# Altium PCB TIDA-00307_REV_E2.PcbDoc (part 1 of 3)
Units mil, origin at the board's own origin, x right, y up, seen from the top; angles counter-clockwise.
Board outline 2360 x 3725 mil, 4 copper layers (Top Layer, L2_GND-PLANE, L3_PWR-PLANE, Bottom Layer), stack 90 mil thick; 312 components, 149 nets, 674 pads, 257 vias.
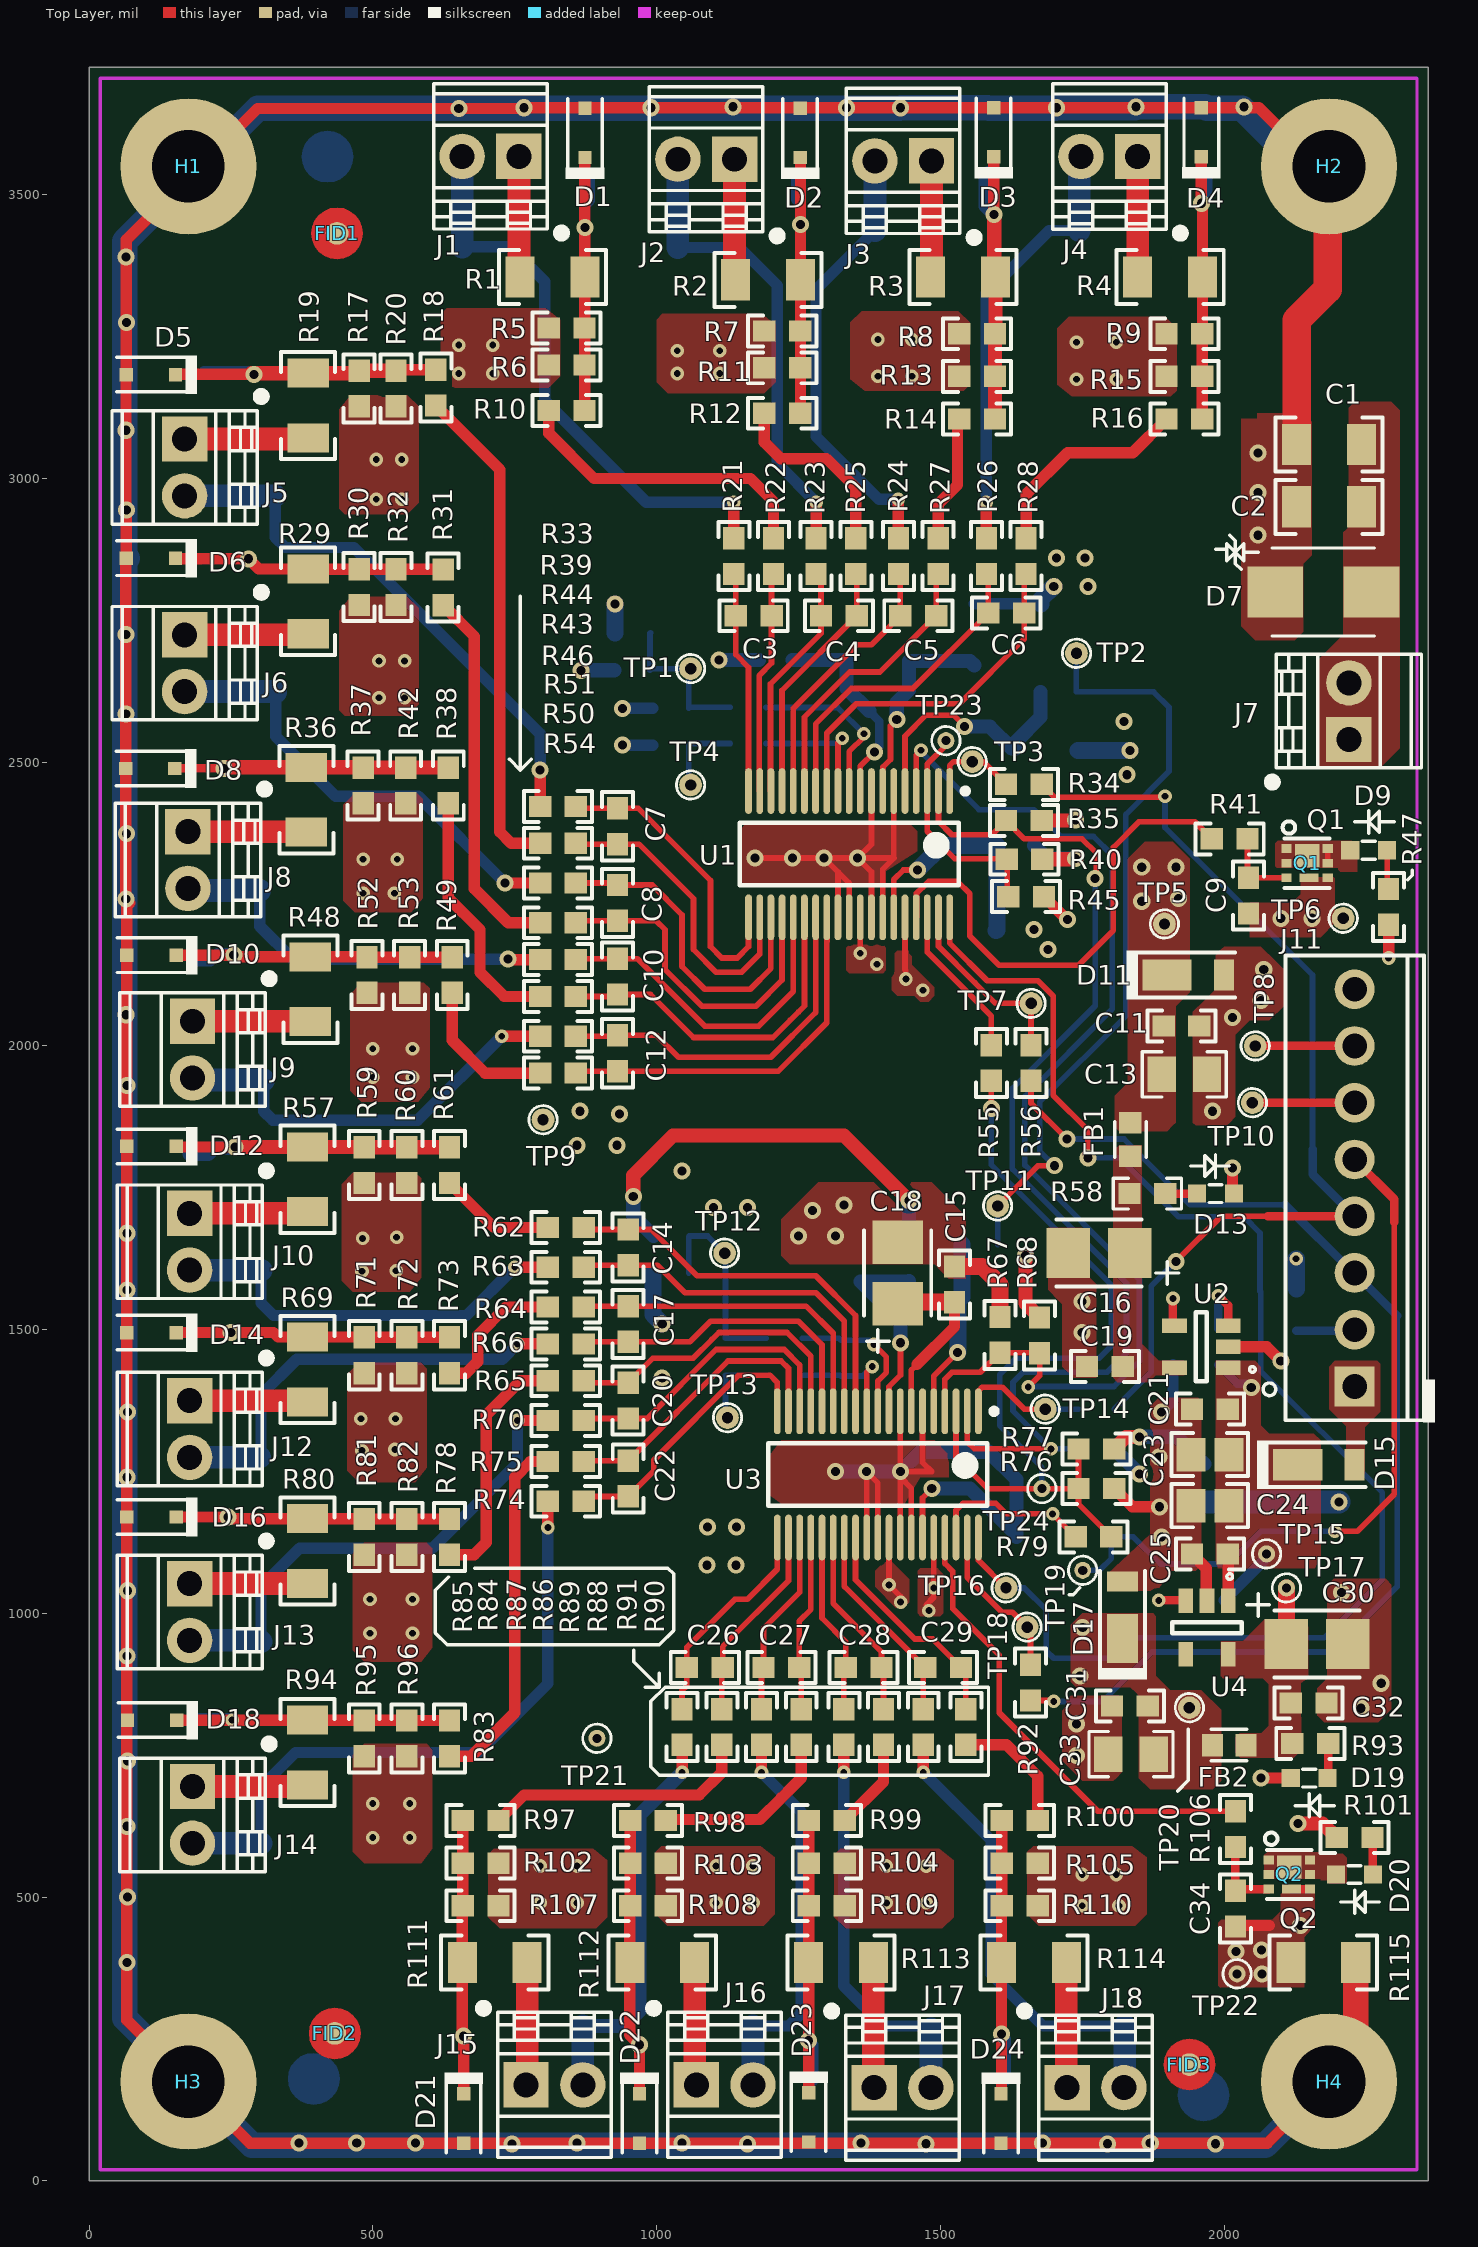
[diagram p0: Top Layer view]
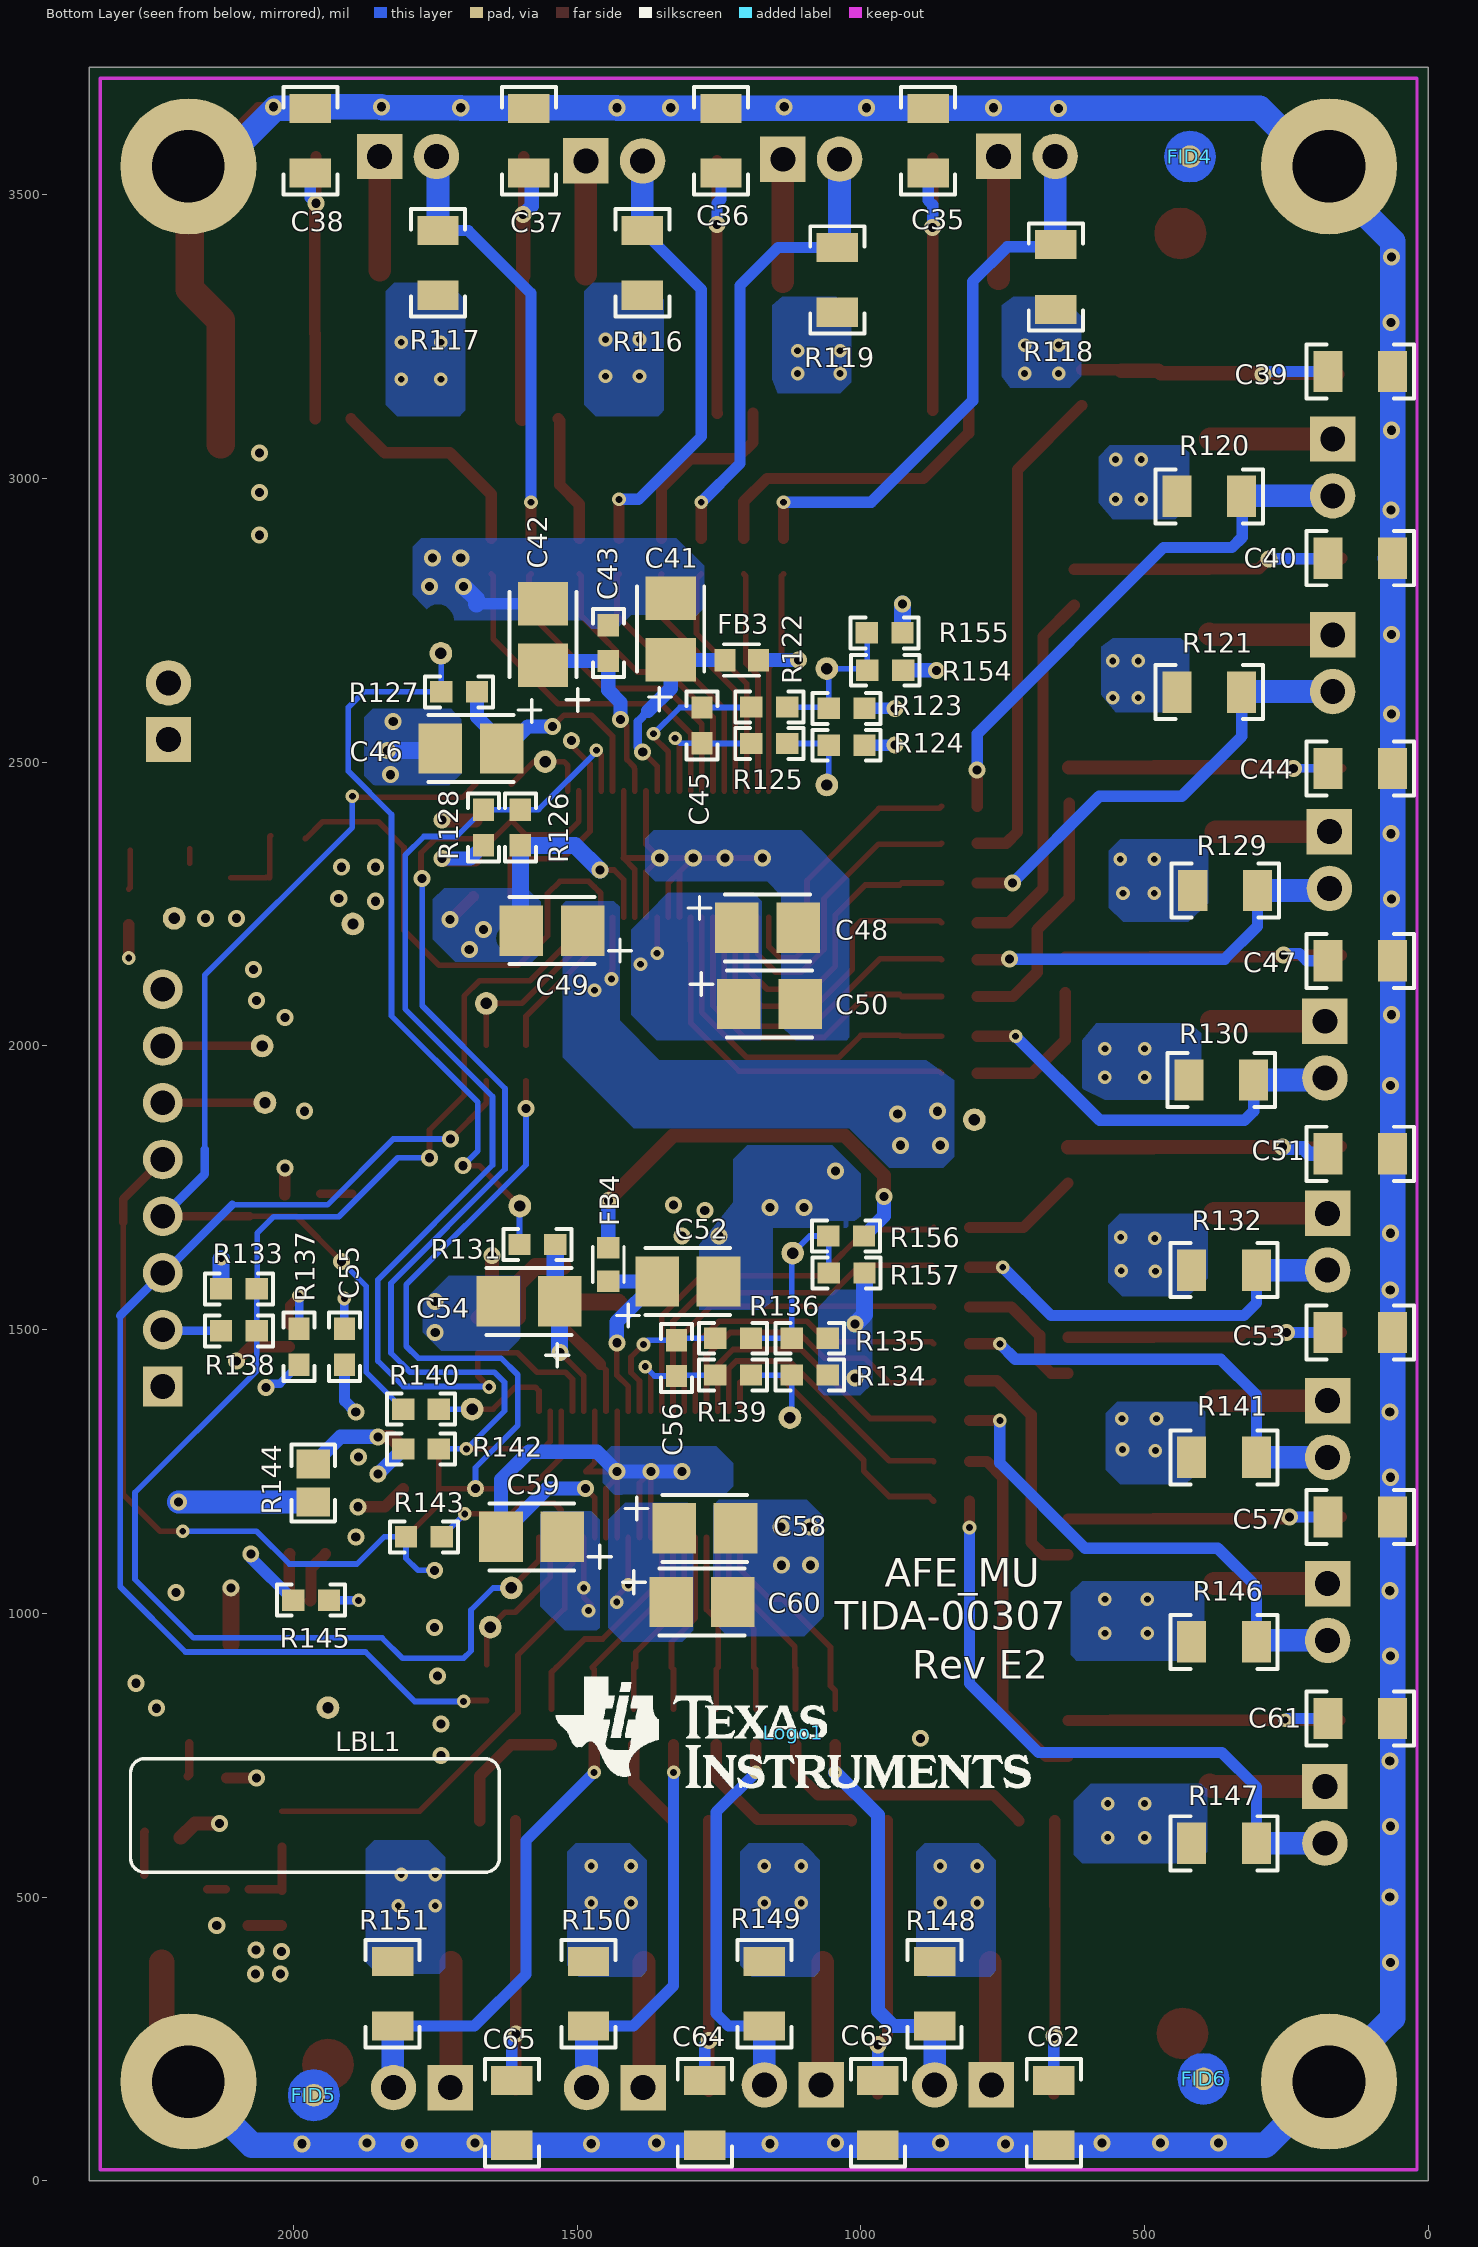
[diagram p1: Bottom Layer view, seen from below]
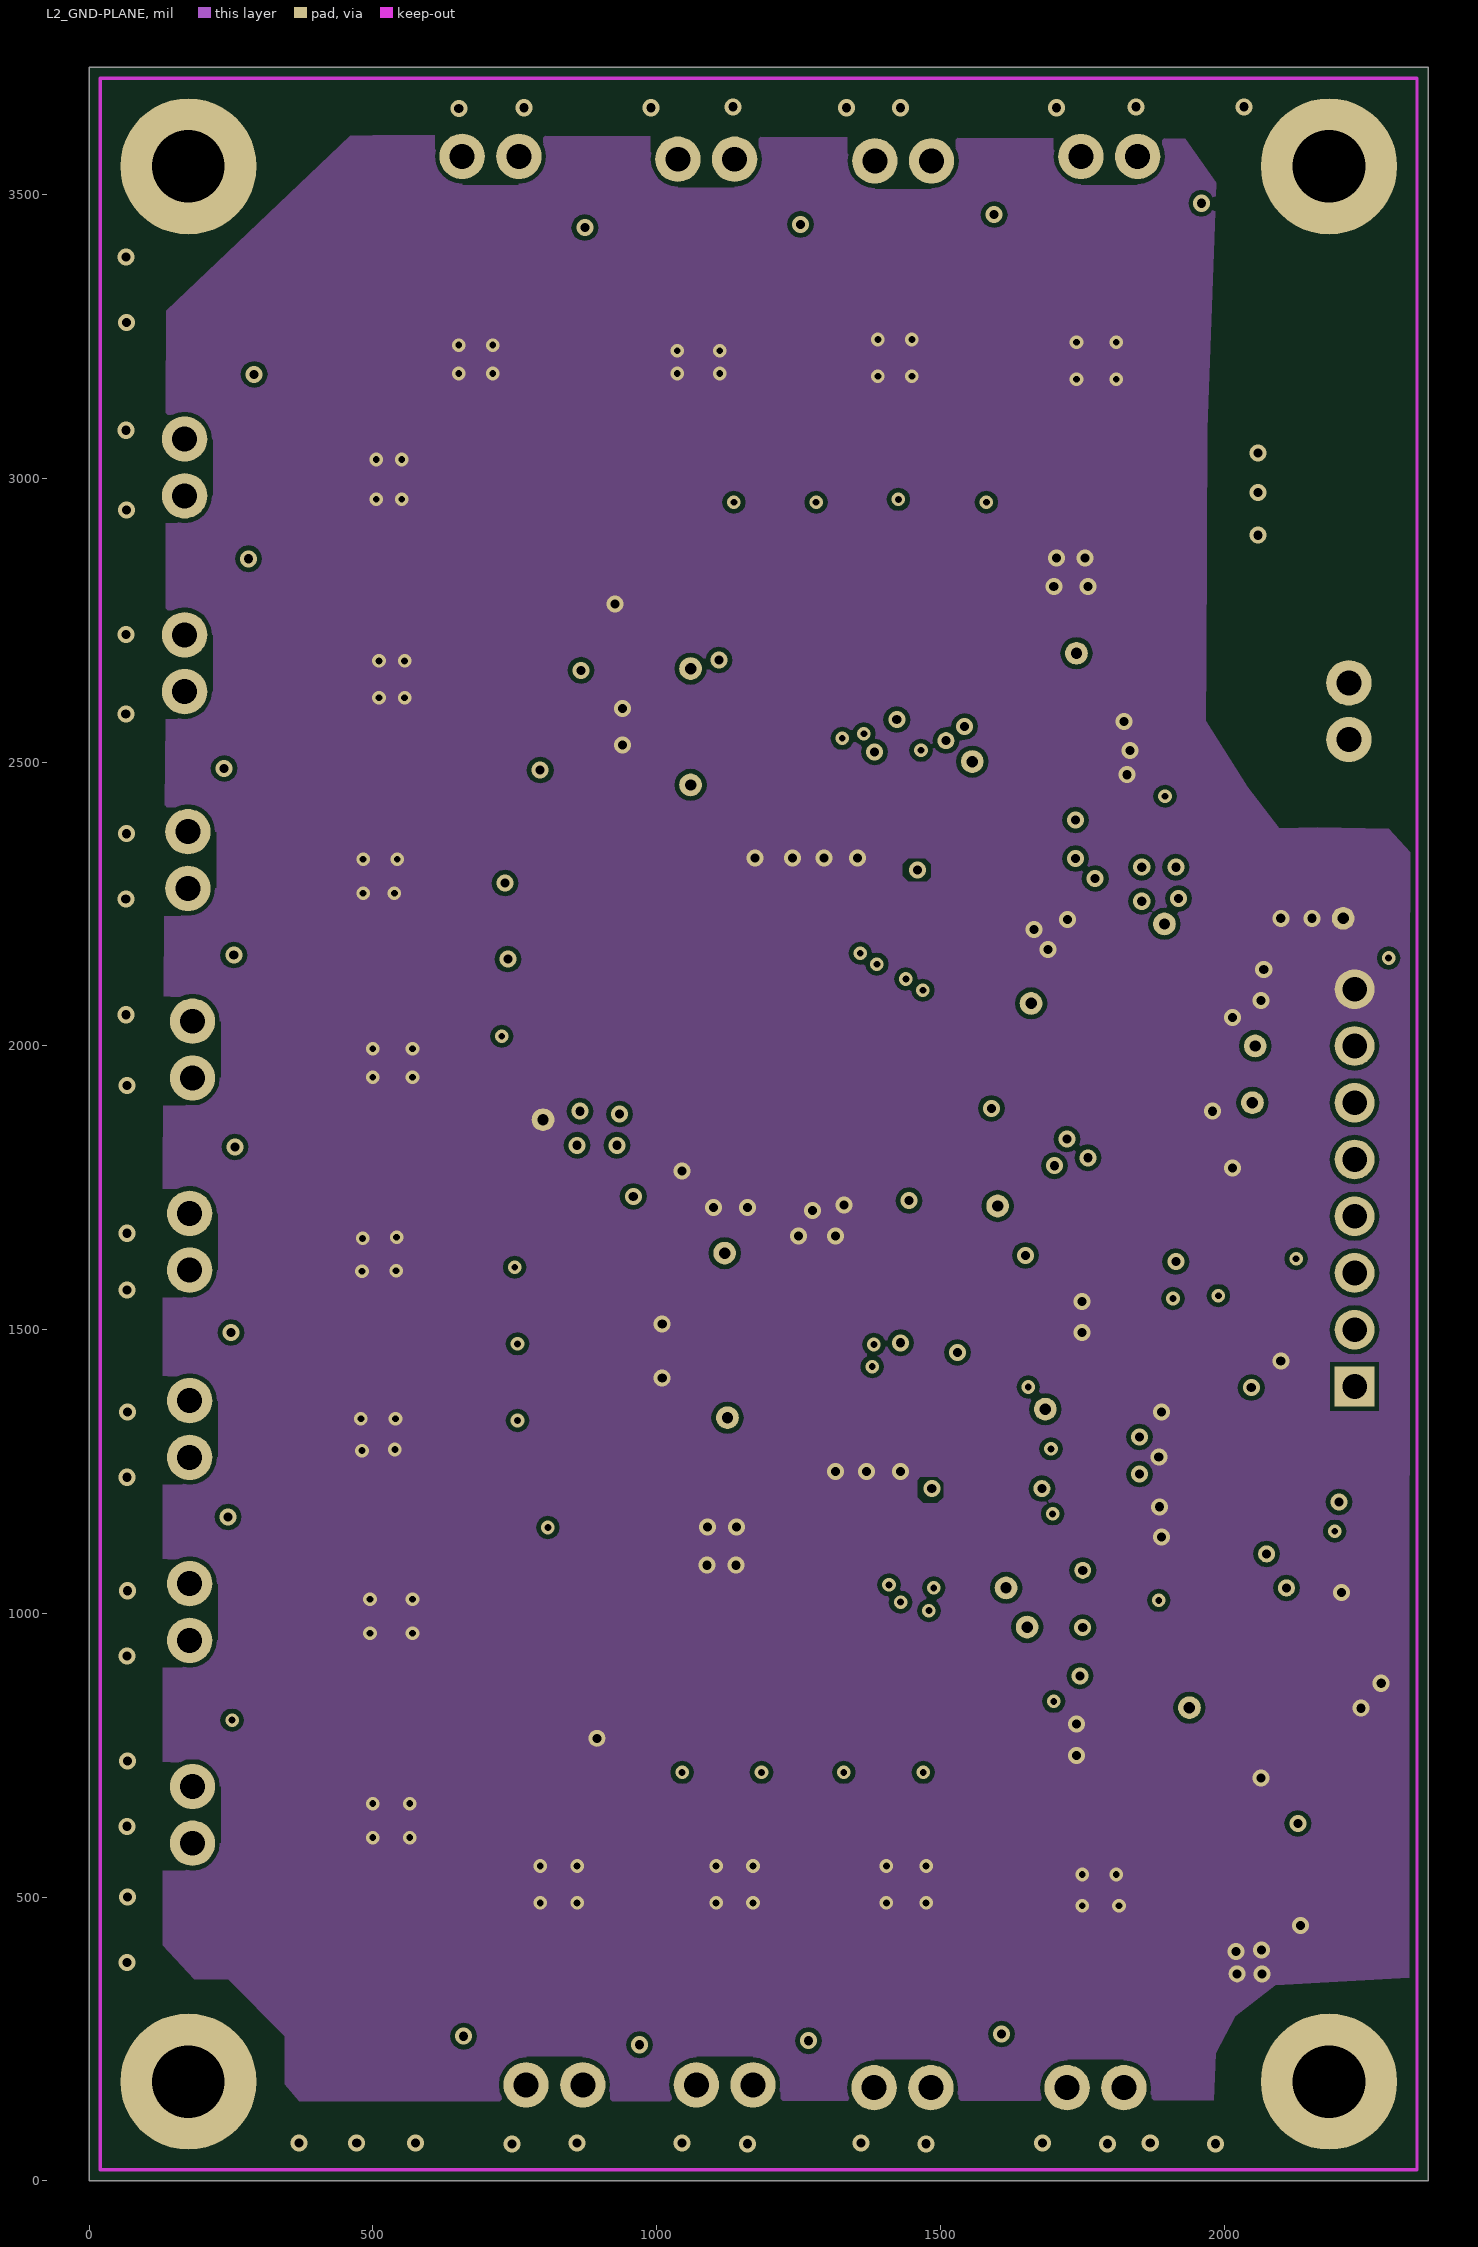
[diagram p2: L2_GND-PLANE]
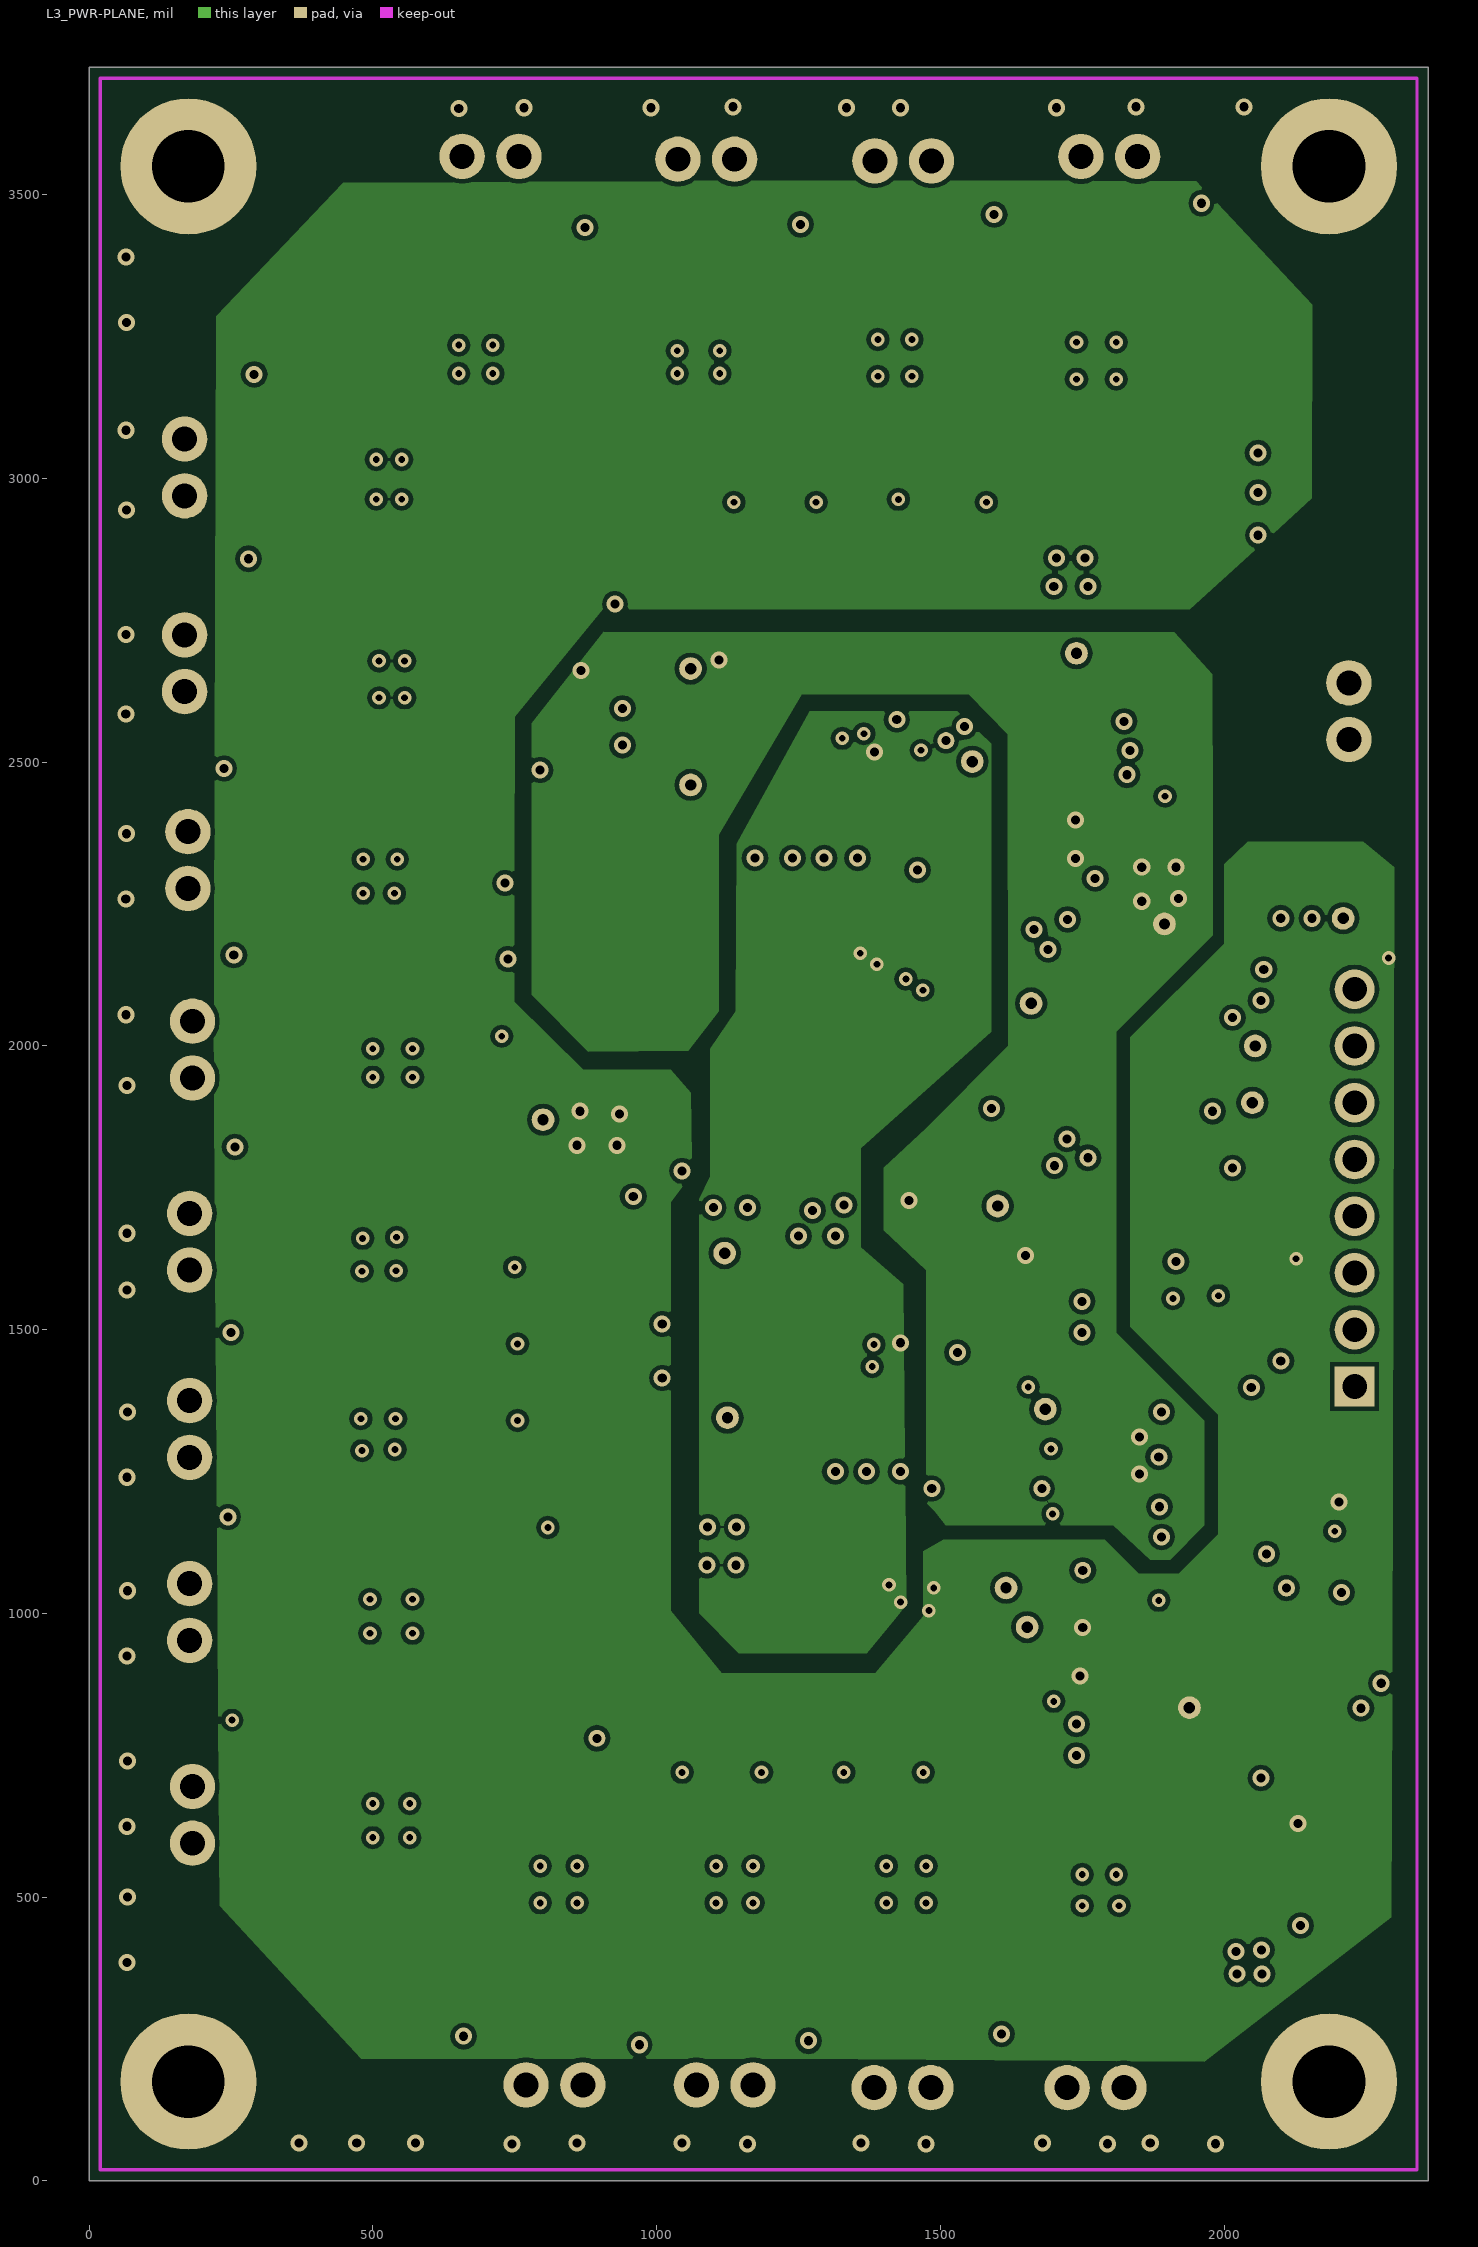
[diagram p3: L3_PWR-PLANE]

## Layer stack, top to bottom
Top Layer: signal copper 1.4
Dielectric: core 59.2, FR-4, Dk 4.8
L2_GND-PLANE: signal copper 1.4
Dielectric: prepreg 12.6, FR-4, Dk 4.8
L3_PWR-PLANE: signal copper 1.4
Dielectric: core 12.6, FR-4, Dk 4.8
Bottom Layer: signal copper 1.4

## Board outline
0,0 2360,0 2360,3725 0,3725

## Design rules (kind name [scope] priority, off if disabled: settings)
AcuteAngle [All] p1: minimum=4.50000000000000E+0001 checktracksonly=FALSE
AssemblyTestPointUsage [All] p1: valid=2
Clearance "U7 AND U9 Pad Class" [(InPadClass('Less Than 7.7')) vs (InPadClass('Less Than 7.7'))] p1: gap=7.8
Clearance Clearance_1 [All] p2: gap=8
Clearance "BOARD EDGE" [IsRegion vs OnLayer('Keep-Out Layer')] p3: gap=25
Clearance "Clearance_Poly to Poly" [InPolygon vs InPolygon] p4: gap=20
Clearance "Clearance_VIA TO VIA" [IsVia vs IsVia] p5: gap=10
Clearance "Clearance_Via to SMD" [IsVia vs IsSMTPin] p6: gap=9
Clearance Clearance_BoardEdge_MountingHoles [(OnLayer('Keep-Out Layer')) vs (InLayerClass('Electrical Layers'))] p7: gap=25
Clearance Clearance_Poly [InPolygon vs IsTrack and IsVia and IsSMTPin and IsThruPin] p8: gap=15
Clearance [InPolygon vs IsVia] p9: gap=8
ComponentClearance ComponentClearance_Logo [InComponentClass('Logo')] p1: gap=50 collisioncheckmode=3 verticalgap=10 showdistances=FALSE
ComponentClearance ComponentClearance_ScrewToNut [(HasFootprint('NY PMS 440 0025 PH')) vs (HasFootprint('Keystone_1902C'))] p2: gap=5 collisioncheckmode=3 verticalgap=10 showdistances=FALSE
ComponentClearance ComponentClearance_MountingHoles [InComponentClass('Mounting Holes')] p3: gap=250 collisioncheckmode=3 verticalgap=100000 showdistances=FALSE
ComponentClearance ComponentClearance_SmallPassives [HasFootprint('0201*') or HasFootprint('0402*') or HasFootprint('0508') or HasFootprint('0603*') or HasFootprint('0612') or HasFootprint('0805*') or HasFootprint('0815*') or HasFootprint('0830*') or HasFootprint('1206*') or HasFootprint('1210*') or HasFootprint('1808*') or HasFootprint('1812*') or HasFootprint('1825*') or HasFootprint('2010*') or HasFootprint('2220*') or HasFootprint('2225*') or HasFootprint('2512*') or HasFootprint('2728*') or HasFootprint('3518*') vs HasFootprint('0201*') or HasFootprint('0402*') or HasFootprint('0508') or HasFootprint('0603*') or HasFootprint('0612') or HasFootprint('0805*') or HasFootprint('0815*') or HasFootprint('0830*') or HasFootprint('1206*') or HasFootprint('1210*') or HasFootprint('1808*') or HasFootprint('1812*') or HasFootprint('1825*') or HasFootprint('2010*') or HasFootprint('2220*') or HasFootprint('2225*') or HasFootprint('2512*') or HasFootprint('2728*') or HasFootprint('3518*')] p4: gap=20 collisioncheckmode=3 verticalgap=10 showdistances=FALSE
ComponentClearance ComponentClearance_THtoSMT [IsThruComponent vs IsSMTComponent] p5: gap=100 collisioncheckmode=3 verticalgap=30 showdistances=FALSE
ComponentClearance ComponentClearance_THtoTH [IsThruComponent vs IsThruComponent] p6: gap=118.11 collisioncheckmode=3 verticalgap=30 showdistances=FALSE
ComponentClearance [All] p7: gap=40 collisioncheckmode=3 verticalgap=10 showdistances=FALSE
DiffPairsRouting [All] p1: maxlimit=100 minlimit=10 mostfreqgap=10 maxuncoupledlength=1000
FabricationTestPointUsage TestPointUsage [All] p1: valid=2 allowmultiple=FALSE
FabricationTestpoint Testpoint [All] p1: side=3 testpointundercomponent=TRUE minsize=40 maxsize=100 preferedsize=60 minholesize=0 maxholesize=40 preferedholesize=32 testpointgrid=1 allowsidetop=TRUE allowsidebottom=TRUE usegrid=TRUE gridtolerance=0.01
FanoutControl Fanout_LCC [IsLCC] p1: bgadir=Out bgaviamode=Centered fanoutstyle=Auto fanoutdirection=Alternating viagrid=1 // Fanout_LCC (Default Rule)
FanoutControl Fanout_BGA [IsBGA] p2: bgadir=Out bgaviamode=Centered fanoutstyle=Auto fanoutdirection=Alternating viagrid=1 // Fanout_BGA (Default Rule)
FanoutControl Fanout_Default [All] p4: bgadir=Out bgaviamode=Centered fanoutstyle=Auto fanoutdirection=Alternating viagrid=1 // Fanout_Default (Default Rule)
FanoutControl Fanout_Small [(CompPinCount < 5)] p5: bgadir=Out bgaviamode=Centered fanoutstyle=Auto fanoutdirection=OutThenIn viagrid=1 // Fanout_Small (Default Rule)
HoleSize [All] p1: absolutevalues=TRUE maxlimit=251 minlimit=7.8 maxpercent=80.000 minpercent=20.000
MinimumAnnularRing MinimumAnnularRing_ThermalPadVias [IsVia and InAnyComponent] p1: minimumring=5.91
MinimumAnnularRing [All] p2: minimumring=6
MinimumSolderMaskSliver MinimumSolderMaskSliver_Logo [InComponentClass('Logo') vs InComponentClass('Logo')] p1: minsoldermaskwidth=0.7
MinimumSolderMaskSliver [All] p2: minsoldermaskwidth=3.94
PlaneClearance [All] p1: clearance=16
PlaneConnect [All] p1: planeconnectstyle=Direct reliefexpansion=10 reliefentries=4 reliefconductorwidth=10 reliefairgap=10
PolygonConnect [All] p1: connectstyle=Direct reliefconductorwidth=10 reliefentries=4 polygonreliefangle="90 Angle" airgapwidth=10
RoutingVias RoutingVias_PWR [InNetClass('PWR')] p1: holewidth=16 width=30 viastyle="Through Hole" minholewidth=12 minwidth=24 maxholewidth=16 maxwidth=30
RoutingVias [InNetClass('All Nets')] p2: holewidth=16 width=30 viastyle="Through Hole" minholewidth=12 minwidth=24 maxholewidth=16 maxwidth=30
RoutingVias ThermalPadVias [IsVia and InAnyComponent] p3: holewidth=7.87 width=19.68 viastyle="Through Hole" minholewidth=7.87 minwidth=19.68 maxholewidth=12.99 maxwidth=23.62
SMDToCorner [All] p1: distance=30000
SilkToSilkClearance [All] p1: silktosilkclearance=5
SilkscreenOverComponentPads [All] p1 off: minsilkscreentomaskgap=5
SolderMaskExpansion [All] p1: expansion=2
Width Width_PWR [InNetClass('pwr')] p1: maxlimit=100 minlimit=8 preferedwidth=30 minimp=50.000000 maximp=50.000000 favimp=50.000000
Width [All] p2: maxlimit=100 minlimit=6 preferedwidth=10 toplayer_minwidth=10 midlayer1_prefwidth=8 midlayer2_prefwidth=8 bottomlayer_minwidth=10 minimp=50.000000 maximp=50.000000 favimp=50.000000 checkconnectedcopper=TRUE
13 further rules are at their usual default settings.

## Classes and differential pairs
component class "Pg3  ADC1,ADC2": C3 C4 C5 C6 C7 C8 C9 C10 C12 C14 C15 C17 C18 C20 C22 C26 C27 C28 C29 C34 C41 C42 C43 C45 C46 C48 C49 C50 C52 C54 C56 C58 C59 C60 D9 D15 D20 FB3 FB4 J11 Q1 Q2 R21 R22 R23 R24 R25 R26 R27 R28 R33 R34 R35 R39 R40 R41 R43 R44 R45 R46 R47 R50 R51 R54 R55 R56 R62 R63 R64 R65 R66 R67 R68 R70 R74 R75 R76 R77 R79 R84 R85 R86 R87 R88 R89 R90 R91 R92 R101 R106 R122 R123 R124 R125 R126 R127 R128 R131 R133 R134 R135 R136 R138 R139 R140 R142 R143 R154 R155 R156 R157 TP1 TP2 TP3 TP4 TP7 TP8 TP10 TP11 TP12 TP13 TP14 TP16 TP18 TP19 TP23 TP24 U1 U3
component class "Pg7 Power Supply": C11 C13 C16 C19 C21 C23 C24 C25 C30 C31 C32 C33 C55 D11 D13 D17 D19 FB1 FB2 R58 R93 R137 R144 R145 TP5 TP15 TP17 TP20 TP21 U2 U4
pad class "Less Than 7.7": U1-1 U1-2 U1-3 U1-4 U1-5 U1-6 U1-7 U1-8 U1-9 U1-10 U1-11 U1-12 U1-13 U1-14 U1-15 U1-16 U1-17 U1-18 U1-19 U1-20 U1-21 U1-22 U1-23 U1-24 U1-25 U1-26 U1-27 U1-28 U1-29 U1-30 U1-31 U1-32 U1-33 U1-34 U1-35 U1-36 U1-37 U1-38 U3-1 U3-2 U3-3 U3-4 U3-5 U3-6 U3-7 U3-8 U3-9 U3-10 U3-11 U3-12 U3-13 U3-14 U3-15 U3-16 U3-17 U3-18 U3-19 U3-20 U3-21 U3-22 U3-23 U3-24 U3-25 U3-26 U3-27 U3-28 U3-29 U3-30 U3-31 U3-32 U3-33 U3-34 U3-35 U3-36 U3-37 U3-38
component class "Pg6 ADC2 FILTERS": C51 C53 C57 C61 C62 C63 C64 C65 D12 D14 D16 D18 D21 D22 D23 D24 R57 R59 R60 R61 R69 R71 R72 R73 R78 R80 R81 R82 R83 R94 R95 R96 R97 R98 R99 R100 R102 R103 R104 R105 R107 R108 R109 R110 R111 R112 R113 R114 TP9
component class "Pg4 ADC1,ADC2 INPUTS": C1 C2 D7 J1 J2 J3 J4 J5 J6 J7 J8 J9 J10 J12 J13 J14 J15 J16 J17 J18 R116 R117 R118 R119 R120 R121 R129 R130 R132 R141 R146 R147 R148 R149 R150 R151 TP22
component class Label: LBL1
component class Logo: Logo1
component class "Pg8 Hardware": !PCB FID1 FID2 FID3 FID4 FID5 FID6 H1 H2 H3 H4 LBL1 Logo1 ZZ1 ZZ2 ZZ3 ZZ4
component class "Mounting Holes": H1 H2 H3 H4
component class "Pg5 ADC1 FILTERS": C35 C36 C37 C38 C39 C40 C44 C47 D1 D2 D3 D4 D5 D6 D8 D10 R1 R2 R3 R4 R5 R6 R7 R8 R9 R10 R11 R12 R13 R14 R15 R16 R17 R18 R19 R20 R29 R30 R31 R32 R36 R37 R38 R42 R48 R49 R52 R53 R115 TP6
component class AssemblyNote: ZZ1 ZZ2 ZZ3 ZZ4

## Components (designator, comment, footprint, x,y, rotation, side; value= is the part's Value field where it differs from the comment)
C1 "202R18W102KV4E" 1206 2185,3060 r0 top (schematic designator C34)
C2 "202R18W102KV4E" 1206 2185,2950 r0 top (schematic designator C30)
C3 "06031C103JAT2A" 0603 1171.22,2758.11 r180 top (schematic designator C82)
C4 "06031C103JAT2A" 0603 1321.22,2758.11 r180 top (schematic designator C81)
C5 "06031C103JAT2A" 0603 1461.22,2758.11 r180 top (schematic designator C80)
C6 "06031C103JAT2A" 0603 1616.22,2763.11 r180 top (schematic designator C79)
C7 "06031C103JAT2A" 0603 931.34,2387.2 r90 top (schematic designator C89)
C8 "06031C103JAT2A" 0603 931.34,2252.2 r90 top (schematic designator C88)
C9 "06033C104JAT2A" 0603 2043,2265 r270 top (schematic designator C130)
C10 "06031C103JAT2A" 0603 931.34,2122.2 r90 top (schematic designator C87)
C11 "C0603C104K5RACTU" 0603 1925,2035 r0 top (schematic designator C91)
C12 "06031C103JAT2A" 0603 931.34,1987.2 r90 top (schematic designator C86)
C13 "C2012X5R1H475K125AB" 0805_HV 1930,1950 r0 top (schematic designator C93)
C14 "06031C103JAT2A" 0603 950,1645 r270 top (schematic designator C115)
C15 "EMK107B7105KA-T" 0603 1525,1580 r270 top (schematic designator C121)
C16 "T491B106K016AT" 3528-21 1780,1635 r180 top (schematic designator C11)
C17 "06031C103JAT2A" 0603 950,1510 r270 top (schematic designator C116)
C18 "T491B106K016AT" 3528-21 1425,1600 r90 top (schematic designator C120)
C19 "C0603C104K5RACTU" 0603 1790,1435 r180 top (schematic designator C40)
C20 "06031C103JAT2A" 0603 950,1375 r270 top (schematic designator C117)
C21 "C0603C104K5RACTU" 0603 1975,1360 r180 top (schematic designator C9)
C22 "06031C103JAT2A" 0603 950.02,1237.73 r270 top (schematic designator C118)
C23 "08055C105KAT2A" 0805 1975,1280 r180 top (schematic designator C13)
C24 "08055C105KAT2A" 0805 1975,1190 r180 top (schematic designator C36)
C25 "C0603C104K5RACTU" 0603 1975,1105 r180 top (schematic designator C41)
C26 "06031C103JAT2A" 0603 1085,905 r180 top (schematic designator C113)
C27 "06031C103JAT2A" 0603 1220,905 r180 top (schematic designator C112)
C28 "06031C103JAT2A" 0603 1365,905 r180 top (schematic designator C111)
C29 "06031C103JAT2A" 0603 1505,905 r180 top (schematic designator C132)
C30 "T491B106K016AT" 3528-21 2164,946 r0 top (schematic designator C45)
C31 "C0603C104K5RACTU" 0603 1834,837 r180 top (schematic designator C91)
C32 "C0603C104K5RACTU" 0603 2149,842 r0 top (schematic designator C47)
C33 "C2012X5R1H475K125AB" 0805_HV 1836,752 r180 top (schematic designator C90)
C34 "06033C104JAT2A" 0603 2020,480 r270 top (schematic designator C132)
C35 "GRM3195C1H273JA01D" 1206 881.5,3595 r90 bottom (schematic designator C16)
C36 "GRM3195C1H273JA01D" 1206 1246.5,3595 r90 bottom (schematic designator C12)
C37 "GRM3195C1H273JA01D" 1206 1585,3595 r90 bottom (schematic designator C55)
C38 "GRM3195C1H273JA01D" 1206 1970,3595 r90 bottom (schematic designator C52)
C39 "GRM3195C1H273JA01D" 1206 120,3188.5 r180 bottom (schematic designator C19)
C40 "GRM3195C1H273JA01D" 1206 120,2859.5 r180 bottom (schematic designator C107)
C41 "T491B106K016AT" 3528-21 1335,2735 r90 bottom (schematic designator C83)
C42 "T491B106K016AT" 3528-21 1560,2725 r90 bottom (schematic designator C76)
C43 "EMK107B7105KA-T" 0603 1445,2710 r270 bottom (schematic designator C77)
C44 "GRM3195C1H273JA01D" 1206 120,2489 r180 bottom (schematic designator C33)
C45 "06031C103JAT2A" 0603 1280,2565 r270 bottom (schematic designator C78)
C46 "T491B106K016AT" 3528-21 1687,2524 r0 bottom (schematic designator C75)
C47 "GRM3195C1H273JA01D" 1206 120,2150 r180 bottom (schematic designator C44)
C48 "T491B106K016AT" 3528-21 1164.33,2208.11 r180 bottom (schematic designator C84)
C49 "T491B106K016AT" 3528-21 1544.33,2203.11 r0 bottom (schematic designator C85)
C50 "T491B106K016AT" 3528-21 1161,2074 r180 bottom (schematic designator C1)
C51 "GRM3195C1H273JA01D" 1206 120,1810 r180 bottom (schematic designator C19)
C52 "T491B106K016AT" 3528-21 1305,1585 r180 bottom (schematic designator C122)
C53 "GRM3195C1H273JA01D" 1206 120,1495 r180 bottom (schematic designator C20)
C54 "T491B106K016AT" 3528-21 1585,1550 r0 bottom (schematic designator C119)
C55 "C0603C103J5RACTU" 0603 1910,1470 r270 bottom (schematic designator C74)
C56 "06031C103JAT2A" 0603 1325,1450 r270 bottom (schematic designator C114)
C57 "GRM3195C1H273JA01D" 1206 120,1170 r180 bottom (schematic designator C13)
C58 "T491B106K016AT" 3528-21 1275,1150 r180 bottom (schematic designator C2)
C59 "T491B106K016AT" 3528-21 1580,1135 r0 bottom (schematic designator C131)
C60 "T491B106K016AT" 3528-21 1280,1020 r180 bottom (schematic designator C109)
C61 "GRM3195C1H273JA01D" 1206 120,815 r180 bottom (schematic designator C14)
C62 "GRM3195C1H273JA01D" 1206 660,120 r270 bottom (schematic designator C17)
C63 "GRM3195C1H273JA01D" 1206 970,120 r270 bottom (schematic designator C18)
C64 "GRM3195C1H273JA01D" 1206 1275,120 r270 bottom (schematic designator C15)
C65 "GRM3195C1H273JA01D" 1206 1615,120 r270 bottom (schematic designator C16)
D1 "CDSOD323-T12C" sod-323 874,3609 r90 top (schematic designator D7)
D2 "CDSOD323-T12C" sod-323 1253,3609 r90 top (schematic designator D11)
D3 "CDSOD323-T12C" sod-323 1594,3610 r90 top (schematic designator D15)
D4 "CDSOD323-T12C" sod-323 1960,3610 r90 top (schematic designator D14)
D5 "CDSOD323-T12C" sod-323 109,3183 r180 top (schematic designator D8)
D6 "CDSOD323-T12C" sod-323 109,2859.5 r180 top (schematic designator D9)
D7 "SMBJ18CA" DIO_SMB_BIAAAA 2175,2800 r0 top (schematic designator D16)
D8 "CDSOD323-T12C" sod-323 108,2489 r180 top (schematic designator D11)
D9 "LED_LG L29K-G2J1-24-Z" LED0603AA 2255,2345 r0 top (schematic designator D27)
D10 "CDSOD323-T12C" sod-323 110,2160 r180 top (schematic designator D13)
D11 "PTZTE255.6B" powerDI123 1950,2125 r0 top (schematic designator D3)
D12 "CDSOD323-T12C" sod-323 110,1823 r180 top (schematic designator D23)
D13 "LED_LG L29K-G2J1-24-Z" LED0603AA 1985,1740 r180 top (schematic designator D2)
D14 "CDSOD323-T12C" sod-323 110,1495 r180 top (schematic designator D24)
D15 "DFLS1200-7" powerDI123 2180,1262 r0 top (schematic designator D25)
D16 "CDSOD323-T12C" sod-323 110,1170 r180 top (schematic designator D17)
D17 "PTZTE255.6B" powerDI123 1821,1006 r90 top (schematic designator D4)
D18 "CDSOD323-T12C" sod-323 111,812 r180 top
D19 "LED_LG L29K-G2J1-24-Z" LED0603AA 2150,710 r0 top (schematic designator D2)
D20 "LED_LG L29K-G2J1-24-Z" LED0603AA 2230,540 r0 top (schematic designator D28)
D21 "CDSOD323-T12C" sod-323 660,110 r270 top
D22 "CDSOD323-T12C" sod-323 970,110 r270 top
D23 "CDSOD323-T12C" sod-323 1268,112 r270 top (schematic designator D19)
D24 "CDSOD323-T12C" sod-323 1607,110 r270 top (schematic designator D20)
FB1 "1000 OHM" FB0603 1835,1835 r90 top (schematic designator FB3)
FB2 "1000 OHM" FB0603 2009,768 r180 top (schematic designator FB3)
FB3 "1000 OHM" FB0603 1210,2680 r0 bottom (schematic designator FB8)
FB4 "1000 OHM" FB0603 1445,1615 r270 bottom (schematic designator FB1)
FID1 "Fiducial40_80" FID_TOP_40_80BA 437,3432 r90 top (schematic designator FID4)
FID2 "Fiducial40_80" FID_TOP_40_80BA 433,260 r90 top
FID3 "Fiducial40_80" FID_TOP_40_80BA 1939,205 r90 top (schematic designator FID6)
FID4 "Fiducial40_80" FID_TOP_40_80BA 420,3567 r90 bottom (schematic designator FID5)
FID5 "Fiducial40_80" FID_TOP_40_80BA 1964,151 r90 bottom (schematic designator FID3)
FID6 "Fiducial40_80" FID_TOP_40_80BA 396,180 r90 bottom (schematic designator FID1)
H1 "NY PMS 440 0025 PH" "NY PMS 440 0025 PH"#1 175,3563 r0 top (schematic designator H4)
H2 "NY PMS 440 0025 PH" "NY PMS 440 0025 PH"#2 2200,3530 r0 top (schematic designator H1)
H3 "NY PMS 440 0025 PH" "NY PMS 440 0025 PH"#3 160,175 r0 top
H4 "NY PMS 440 0025 PH" "NY PMS 440 0025 PH"#4 2200,175 r0 top (schematic designator H2)
J1 "CON-OSTVN02A150" CN2_MTB_P100_PD80_D1.1_S5.54X6.5_STACK 707.5,3567.56 r180 top (schematic designator J16)
J2 "CON-OSTVN02A150" CN2_MTB_P100_PD80_D1.1_S5.54X6.5_STACK 1087.5,3562.56 r180 top (schematic designator J14)
J3 "CON-OSTVN02A150" CN2_MTB_P100_PD80_D1.1_S5.54X6.5_STACK 1434.59,3559.68 r180 top (schematic designator J21)
J4 "CON-OSTVN02A150" CN2_MTB_P100_PD80_D1.1_S5.54X6.5_STACK 1797.87,3567.3 r180 top (schematic designator J20)
J5 "CON-OSTVN02A150" CN2_MTB_P100_PD80_D1.1_S5.54X6.5_STACK 168.44,3019.5 r270 top (schematic designator J15)
J6 "CON-OSTVN02A150" CN2_MTB_P100_PD80_D1.1_S5.54X6.5_STACK 168.44,2674.5 r270 top (schematic designator J17)
J7 "CON-OSTVN02A150" CN2_MTB_P100_PD80_D1.1_S5.54X6.5_STACK 2220,2590 r90 top (schematic designator J9)
J8 "CON-OSTVN02A150" CN2_MTB_P100_PD80_D1.1_S5.54X6.5_STACK 174.26,2327.59 r270 top (schematic designator J18)
J9 "CON-OSTVN02A150" CN2_MTB_P100_PD80_D1.1_S5.54X6.5_STACK 182.32,1993.59 r270 top (schematic designator J19)
J10 "CON-OSTVN02A150" CN2_MTB_P100_PD80_D1.1_S5.54X6.5_STACK 177.32,1655.09 r270 top (schematic designator J7)
J11 "1725711" CONN_1725711 2230,1750 r90 top (schematic designator J13)
J12 "CON-OSTVN02A150" CN2_MTB_P100_PD80_D1.1_S5.54X6.5_STACK 177.32,1325.09 r270 top (schematic designator J8)
J13 "CON-OSTVN02A150" CN2_MTB_P100_PD80_D1.1_S5.54X6.5_STACK 177.32,1002.64 r270 top (schematic designator J1)
J14 "CON-OSTVN02A150" CN2_MTB_P100_PD80_D1.1_S5.54X6.5_STACK 182.32,645.09 r270 top (schematic designator J2)
J15 "CON-OSTVN02A150" CN2_MTB_P100_PD80_D1.1_S5.54X6.5_STACK 820,169.29 r0 top (schematic designator J3)
J16 "CON-OSTVN02A150" CN2_MTB_P100_PD80_D1.1_S5.54X6.5_STACK 1120,169.29 r0 top (schematic designator J4)
J17 "CON-OSTVN02A150" CN2_MTB_P100_PD80_D1.1_S5.54X6.5_STACK 1433.5,164.29 r0 top (schematic designator J5)
J18 "CON-OSTVN02A150" CN2_MTB_P100_PD80_D1.1_S5.54X6.5_STACK 1773.5,164.29 r0 top (schematic designator J6)
LBL1 "Size: 0.65\" x 0.20 \"" Label_650x200 1962,644 r180 bottom
Logo1 "Texas Instruments" TI_Stacked_SolderMask_Small 1119,790 r180 bottom
Q1 "CSD17571Q2" SON_CSD17571Q2 2146.32,2322 r270 top
Q2 "CSD17571Q2" SON_CSD17571Q2 2115,540 r270 top
R1 "MMA02040C1000FB300" 1206 816.5,3355 r0 top (schematic designator R10)
R2 "MMA02040C1000FB300" 1206 1196.5,3350 r0 top (schematic designator R156)
R3 "MMA02040C1000FB300" 1206 1540,3355 r0 top (schematic designator R55)
R4 "MMA02040C1000FB300" 1206 1905,3355 r0 top (schematic designator R42)
R5 "CRCW060322R0FKEA" 0603 841.5,3265 r0 top (schematic designator R17)
R6 "CRCW060322R0FKEA" 0603 841.5,3200 r0 top (schematic designator R135)
R7 "CRCW060322R0FKEA" 0603 1221.5,3260 r0 top (schematic designator R8)
R8 "CRCW060322R0FKEA" 0603 1565,3255 r0 top (schematic designator R58)
R9 "CRCW060322R0FKEA" 0603 1930,3255 r0 top (schematic designator R50)
R10 "CRCW06031K00FKEA" 0603 841.5,3120 r180 top (schematic designator R35)
R11 "CRCW060322R0FKEA" 0603 1221.5,3195 r0 top (schematic designator R134)
R12 "CRCW06031K00FKEA" 0603 1221.5,3115 r180 top (schematic designator R21)
R13 "CRCW060322R0FKEA" 0603 1565,3180 r0 top (schematic designator R141)
R14 "CRCW06031K00FKEA" 0603 1565,3105 r180 top (schematic designator R54)
R15 "CRCW060322R0FKEA" 0603 1930,3180 r0 top (schematic designator R140)
R16 "CRCW06031K00FKEA" 0603 1930,3105 r180 top (schematic designator R53)
R17 "CRCW060322R0FKEA" 0603 476,3158.5 r90 top (schematic designator R9)
R18 "CRCW06031K00FKEA" 0603 611,3160 r270 top (schematic designator R9)
R19 "MMA02040C1000FB300" 1206 386,3128.5 r90 top (schematic designator R22)
R20 "CRCW060322R0FKEA" 0603 541,3158.5 r90 top (schematic designator R136)
R21 "CRCW06031K60JNEA" 0603 1136.22,2863.11 r270 top (schematic designator R118)
R22 "RC0603JR-070RL" 0603 1206.22,2863.11 r270 top (schematic designator R117)
R23 "CRCW06031K60JNEA" 0603 1281.22,2863.11 r270 top (schematic designator R116)
R24 "CRCW06031K60JNEA" 0603 1426.22,2863.11 r270 top (schematic designator R114)
R25 "RC0603JR-070RL" 0603 1351.22,2863.11 r270 top (schematic designator R115)
R26 "CRCW06031K60JNEA" 0603 1581.22,2863.11 r270 top (schematic designator R112)
R27 "RC0603JR-070RL" 0603 1496.22,2863.11 r270 top (schematic designator R113)
R28 "RC0603JR-070RL" 0603 1651.22,2863.11 r270 top (schematic designator R111)
R29 "MMA02040C1000FB300" 1206 386,2783.5 r90 top (schematic designator R26)
R30 "CRCW060322R0FKEA" 0603 476,2808.5 r90 top (schematic designator R25)
R31 "CRCW06031K00FKEA" 0603 624,2808 r270 top (schematic designator R8)
R32 "CRCW060322R0FKEA" 0603 541,2808.5 r90 top (schematic designator R137)
R33 "CRCW06031K60JNEA" 0603 826.34,2422.2 r180 top (schematic designator R130)
R34 "RC0603JR-070RL" 0603 1647.33,2461.11 r180 top (schematic designator R102)
R35 "CRCW060347K0FKEA" 0603 1647.33,2397.11 r180 top (schematic designator R103)
R36 "MMA02040C1000FB300" 1206 383,2434 r90 top (schematic designator R29)
R37 "CRCW060322R0FKEA" 0603 483,2459 r90 top (schematic designator R31)
R38 "CRCW06031K00FKEA" 0603 633,2459 r270 top (schematic designator R7)
R39 "RC0603JR-070RL" 0603 826.34,2357.2 r180 top (schematic designator R129)
R40 "CRCW060347K0FKEA" 0603 1648.33,2329.11 r180 top (schematic designator R104)
R41 "CRCW0603300RJNEA" 0603 2010,2365 r0 top (schematic designator R187)
R42 "CRCW060322R0FKEA" 0603 558,2459 r90 top (schematic designator R138)
R43 "RC0603JR-070RL" 0603 826.34,2217.2 r180 top (schematic designator R127)
R44 "CRCW06031K60JNEA" 0603 826.34,2287.2 r180 top (schematic designator R128)
R45 "CRCW060347K0FKEA" 0603 1651.33,2263.11 r180 top (schematic designator R105)
R46 "CRCW06031K60JNEA" 0603 826.34,2152.2 r180 top (schematic designator R126)
R47 "CRCW0603300RJNEA" 0603 2290,2245 r270 top (schematic designator R189)
R48 "MMA02040C1000FB300" 1206 390,2100 r90 top (schematic designator R39)
R49 "CRCW06031K00FKEA" 0603 640,2125 r270 top (schematic designator R6)
R50 "CRCW06031K60JNEA" 0603 826.34,2017.2 r180 top (schematic designator R124)
R51 "RC0603JR-070RL" 0603 826.34,2087.2 r180 top (schematic designator R125)
R52 "CRCW060322R0FKEA" 0603 490,2125 r90 top (schematic designator R40)
R53 "CRCW060322R0FKEA" 0603 565,2125 r90 top (schematic designator R139)
R54 "RC0603JR-070RL" 0603 826.34,1952.2 r180 top (schematic designator R123)
R55 "RC0603JR-070RL" 0603 1590,1970 r270 top (schematic designator R121)
R56 "RC0603JR-070RL" 0603 1660,1970 r270 top (schematic designator R120)
R57 "MMA02040C1000FB300" 1206 385,1765 r90 top (schematic designator R163)
R58 "CRCW0603560RJNEA" 0603 1865,1740 r180 top (schematic designator R79)
R59 "CRCW060322R0FKEA" 0603 485,1790 r90 top (schematic designator R151)
R60 "CRCW060322R0FKEA" 0603 560,1790 r90 top (schematic designator R152)
R61 "CRCW06031K00FKEA" 0603 635,1790 r270 top (schematic designator R153)
R62 "RC0603JR-070RL" 0603 840,1680 r0 top (schematic designator R117)
R63 "CRCW06031K60JNEA" 0603 840,1610 r0 top (schematic designator R122)
R64 "RC0603JR-070RL" 0603 840,1540 r0 top (schematic designator R118)
R65 "RC0603JR-070RL" 0603 840,1410 r0 top (schematic designator R119)
R66 "CRCW06031K60JNEA" 0603 840,1475 r0 top (schematic designator R123)
R67 "CRCW060347K0FKEA" 0603 1605,1490.94 r90 top (schematic designator R158)
R68 "CRCW060347K0FKEA" 0603 1675,1490 r270 top (schematic designator R133)
R69 "MMA02040C1000FB300" 1206 385,1430 r90 top (schematic designator R164)
R70 "CRCW06031K60JNEA" 0603 840,1340 r0 top (schematic designator R124)
R71 "CRCW060322R0FKEA" 0603 485,1455 r90 top (schematic designator R154)
R72 "CRCW060322R0FKEA" 0603 560,1455 r90 top (schematic designator R176)
R73 "CRCW06031K00FKEA" 0603 635,1455 r270 top (schematic designator R178)
R74 "CRCW06031K60JNEA" 0603 840,1197.73 r0 top (schematic designator R125)
R75 "RC0603JR-070RL" 0603 840,1267.73 r0 top (schematic designator R155)
R76 "CRCW060347K0FKEA" 0603 1775,1220 r180 top (schematic designator R132)
R77 "CRCW060347K0FKEA" 0603 1775,1290 r180 top (schematic designator R131)
R78 "CRCW06031K00FKEA" 0603 635,1135 r270 top (schematic designator R93)
R79 "RC0603JR-070RL" 0603 1770,1135 r180 top (schematic designator R133)
R80 "MMA02040C1000FB300" 1206 385,1110 r90 top (schematic designator R157)
R81 "CRCW060322R0FKEA" 0603 485,1135 r90 top (schematic designator R91)
R82 "CRCW060322R0FKEA" 0603 560,1135 r90 top (schematic designator R92)
R83 "CRCW06031K00FKEA" 0603 635,780 r270 top (schematic designator R96)
R84 "RC0603JR-070RL" 0603 1115,800 r270 top (schematic designator R111)
R85 "CRCW06031K60JNEA" 0603 1045,800 r270 top (schematic designator R114)
R86 "RC0603JR-070RL" 0603 1255,800 r270 top (schematic designator R108)
R87 "CRCW06031K60JNEA" 0603 1185,800 r270 top (schematic designator R112)
R88 "RC0603JR-070RL" 0603 1400,800 r270 top (schematic designator R105)
R89 "CRCW06031K60JNEA" 0603 1330,800 r270 top (schematic designator R109)
R90 "RC0603JR-070RL" 0603 1545,800 r270 top (schematic designator R104)
R91 "CRCW06031K60JNEA" 0603 1470,800 r270 top (schematic designator R106)
R92 "RC0603JR-070RL" 0603 1659,878 r270 top (schematic designator R51)
R93 "CRCW0603560RJNEA" 0603 2152,771 r180 top (schematic designator R148)
R94 "MMA02040C1000FB300" 1206 385,755 r90 top (schematic designator R158)
R95 "CRCW060322R0FKEA" 0603 485,780 r90 top (schematic designator R94)
R96 "CRCW060322R0FKEA" 0603 560,780 r90 top (schematic designator R95)
R97 "CRCW06031K00FKEA" 0603 690,635 r0 top (schematic designator R167)
R98 "CRCW06031K00FKEA" 0603 985,635 r0 top (schematic designator R170)
R99 "CRCW06031K00FKEA" 0603 1300,635 r0 top
R100 "CRCW06031K00FKEA" 0603 1640,635 r0 top (schematic designator R175)
R101 "CRCW0603300RJNEA" 0603 2230,605 r180 top (schematic designator R190)
R102 "CRCW060322R0FKEA" 0603 690,560 r180 top (schematic designator R168)
R103 "CRCW060322R0FKEA" 0603 985,560 r180 top (schematic designator R181)
R104 "CRCW060322R0FKEA" 0603 1300,560 r180 top (schematic designator R98)
R105 "CRCW060322R0FKEA" 0603 1640,560 r180 top (schematic designator R143)
R106 "CRCW0603300RJNEA" 0603 2020,620 r270 top (schematic designator R188)
R107 "CRCW060322R0FKEA" 0603 690,485 r180 top (schematic designator R169)
R108 "CRCW060322R0FKEA" 0603 985,485 r180 top (schematic designator R180)
R109 "CRCW060322R0FKEA" 0603 1300,485 r180 top (schematic designator R97)
R110 "CRCW060322R0FKEA" 0603 1640,485 r180 top (schematic designator R142)
R111 "MMA02040C1000FB300" 1206 715,385 r180 top (schematic designator R161)
R112 "MMA02040C1000FB300" 1206 1010,385 r180 top (schematic designator R162)
R113 "MMA02040C1000FB300" 1206 1325,385 r180 top (schematic designator R159)
R114 "MMA02040C1000FB300" 1206 1665,385 r180 top (schematic designator R160)
R115 "RC1206JR-070RL" 1206 2175,385 r0 top (schematic designator R3)
R116 "RC1206JR-070RL" 1206 1385,3380 r90 bottom (schematic designator R174)
R117 "RC1206JR-070RL" 1206 1745,3380 r90 bottom (schematic designator R147)
R118 "RC1206JR-070RL" 1206 656.5,3355 r90 bottom (schematic designator R185)
R119 "RC1206JR-070RL" 1206 1041.5,3350 r90 bottom (schematic designator R171)
R120 "RC1206JR-070RL" 1206 386,2968.5 r180 bottom (schematic designator R172)
R121 "RC1206JR-070RL" 1206 386,2623.5 r180 bottom (schematic designator R150)
R122 "CRCW0603357RFKEA" 0603 1161.33,2597.11 r0 bottom (schematic designator R108)
R123 "RC0603JR-070RL" 0603 1025,2595 r0 bottom (schematic designator R109)
R124 "RC0603JR-070RL" 0603 1025,2530 r0 bottom (schematic designator R119)
R125 "CRCW0603357RFKEA" 0603 1161.33,2533.11 r0 bottom (schematic designator R110)
R126 "CRCW060347K0FKEA" 0603 1600,2385 r270 bottom (schematic designator R107)
R127 "RC0603JR-070RL" 0603 1708,2624 r180 bottom (schematic designator R144)
R128 "CRCW060347K0FKEA" 0603 1665,2385 r90 bottom (schematic designator R106)
R129 "RC1206JR-070RL" 1206 358,2274 r180 bottom (schematic designator R186)
R130 "RC1206JR-070RL" 1206 365,1940 r180 bottom (schematic designator R173)
R131 "RC0603JR-070RL" 0603 1570,1650 r180 bottom (schematic designator R145)
R132 "RC1206JR-070RL" 1206 360,1605 r180 bottom (schematic designator R87)
R133 "CRCW060347K0FKEA" 0603 2096,1572 r180 bottom (schematic designator R41)
R134 "RC0603JR-070RL" 0603 1090,1420 r0 bottom (schematic designator R126)
R135 "RC0603JR-070RL" 0603 1090,1485 r0 bottom (schematic designator R150)
R136 "CRCW0603357RFKEA" 0603 1225,1485 r0 bottom (schematic designator R116)
R137 "CRCW060310K0FKEA" 0603 1990,1470 r270 bottom (schematic designator R101)
R138 "RC0603JR-070RL" 0603 2096,1498 r180 bottom (schematic designator R146)
R139 "CRCW0603357RFKEA" 0603 1225,1420 r0 bottom (schematic designator R121)
R140 "RC0603JR-070RL" 0603 1775,1360 r180 bottom (schematic designator R52)
R141 "RC1206JR-070RL" 1206 360,1275 r180 bottom (schematic designator R89)
R142 "CRCW060347K0FKEA" 0603 1775,1290 r180 bottom (schematic designator R131)
R143 "RC0603JR-070RL" 0603 1770,1135 r0 bottom (schematic designator R142)
R144 "RC0805JR-070RL" 0805 1965,1230 r270 bottom (schematic designator R4)
R145 "CRCW060310K0FKEA" 0603 1968.81,1023.43 r0 bottom (schematic designator R149)
R146 "RC1206JR-070RL" 1206 360,950 r180 bottom (schematic designator R61)
R147 "RC1206JR-070RL" 1206 360,595 r180 bottom (schematic designator R64)
R148 "RC1206JR-070RL" 1206 870,330 r270 bottom (schematic designator R71)
R149 "RC1206JR-070RL" 1206 1170,330 r270 bottom (schematic designator R73)
R150 "RC1206JR-070RL" 1206 1480,330 r270 bottom (schematic designator R76)
R151 "RC1206JR-070RL" 1206 1825,330 r270 bottom (schematic designator R78)
R154 "CRCW060347K0FKEA" 0603 957,2662 r180 bottom
R155 "CRCW060347K0FKEA" 0603 958,2728 r0 bottom
R156 "CRCW060347K0FKEA" 0603 1026,1665 r180 bottom
R157 "CRCW060347K0FKEA" 0603 1025,1600 r0 bottom
TP1 "TP1_PD40_D0.5_S50" TP1_PD40_D0.5_S50#1 1060,2665 r270 top (schematic designator TP29)
TP2 "TP1_PD40_D0.5_S50" TP1_PD40_D0.5_S50#1 1740,2692 r270 top (schematic designator TP26)
TP3 "TP1_PD40_D0.5_S50" TP1_PD40_D0.5_S50#1 1556.33,2501.11 r270 top (schematic designator TP27)
TP4 "TP1_PD40_D0.5_S50" TP1_PD40_D0.5_S50#1 1060,2460 r270 top (schematic designator TP28)
TP5 "TP1_PD40_D0.5_S50" TP1_PD40_D0.5_S50#1 1895,2215 r90 top (schematic designator TP23)
TP6 "TP1_PD40_D0.5_S50" TP1_PD40_D0.5_S50#1 2210,2225 r90 top (schematic designator TP18)
TP7 "TP1_PD40_D0.5_S50" TP1_PD40_D0.5_S50#1 1660,2075 r270 top (schematic designator TP26)
TP8 "TP1_PD40_D0.5_S50" TP1_PD40_D0.5_S50#1 2055,2000 r90 top (schematic designator TP39)
TP9 "TP1_PD40_D0.5_S50" TP1_PD40_D0.5_S50#1 800,1870 r90 top (schematic designator TP34)
TP10 "TP1_PD40_D0.5_S50" TP1_PD40_D0.5_S50#1 2050,1900 r90 top (schematic designator TP40)
TP11 "TP1_PD40_D0.5_S50" TP1_PD40_D0.5_S50#1 1601,1718 r90 top (schematic designator TP38)
TP12 "TP1_PD40_D0.5_S50" TP1_PD40_D0.5_S50#1 1120,1635 r90 top (schematic designator TP21)
TP13 "TP1_PD40_D0.5_S50" TP1_PD40_D0.5_S50#1 1125,1345 r90 top (schematic designator TP20)
TP14 "TP1_PD40_D0.5_S50" TP1_PD40_D0.5_S50#1 1685,1360 r90 top (schematic designator TP16)
TP15 "TP1_PD40_D0.5_S50" TP1_PD40_D0.5_S50#2 2075,1105 r90 top (schematic designator TP7)
TP16 "TP1_PD40_D0.5_S50" TP1_PD40_D0.5_S50#1 1615.91,1045 r180 top (schematic designator TP13)
TP17 "TP1_PD40_D0.5_S50" TP1_PD40_D0.5_S50#2 2110,1045 r270 top
TP18 "TP1_PD40_D0.5_S50" TP1_PD40_D0.5_S50#1 1653,976 r180 top (schematic designator TP14)
TP19 "TP1_PD40_D0.5_S50" TP1_PD40_D0.5_S50#2 1751,1076 r90 top (schematic designator TP15)
TP20 "TP1_PD40_D0.5_S50" TP1_PD40_D0.5_S50#1 1939,834 r180 top (schematic designator TP2)
TP21 "TP1_PD40_D0.5_S50" TP1_PD40_D0.5_S50#2 895,780 r90 top (schematic designator TP18)
TP22 "TP1_PD40_D0.5_S50" TP1_PD40_D0.5_S50#2 2023,365 r90 top (schematic designator TP8)
TP23 "TP1_PD40_D0.5_S50" TP1_PD40_D0.5_S50#2 1510,2538 r90 top
TP24 "TP1_PD40_D0.5_S50" TP1_PD40_D0.5_S50#2 1679,1220 r90 top
U1 "ADS8688DBT" DBT0038A_M 1339.33,2337.99 r270 top (schematic designator U18)
U2 "TPS70950DBVR" DBV0005A_N 1960,1470 r180 top (schematic designator U1)
U3 "ADS8688DBT" DBT0038A_M 1390,1245 r270 top (schematic designator U5)
U4 "TPS70933DBVT" DBV0005A_N 1970,975 r270 top (schematic designator U11)
ZZ1 "This Assembly Note is for PCB labels only" AssemblyNoteLabel 209,4751 r0 top
ZZ2 "These assemblies must be clean and free from flux and all contaminants. Use of no clean flux is not acceptable." AssemblyNote 209,4644 r0 top
ZZ3 "These assemblies are ESD sensitive, ESD precautions shall be observed." AssemblyNote 207,4536 r0 top
ZZ4 "These assemblies must comply with workmanship standards IPC-A-610 Class 2, unless otherwise specified." AssemblyNote 206,4416 r0 top

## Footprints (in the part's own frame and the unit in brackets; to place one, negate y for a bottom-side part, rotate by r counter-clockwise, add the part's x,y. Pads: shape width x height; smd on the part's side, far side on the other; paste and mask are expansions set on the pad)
0603 [mm] "0603 from SM-752 data"
  rect 1x0.95 smd: 1(-0.8,0) 2(0.8,0)
  silkscreen extent -1.52,-0.69 1.52,0.69, body extent -0.87,-0.47 0.87,0.47, height 0.85
0805 [mm] "0805 from SM-752 data"
  rect 1.3x1.5 smd: 1(-0.85,0) 2(0.85,0)
  silkscreen extent -1.72,-0.97 1.72,0.97, body extent -1.1,-0.72 1.1,0.72, height 1.1
0805_HV [mil] "0805 with 30mil clearance between pads"
  rect 50x63 smd: 1(-40,0) 2(40,0)
  silkscreen extent -74,-40 74,40, body extent -43,-29 43,29, height 43
1206 [mm] "1206 from SM-752 data"
  rect 1.3x1.85 smd: 1(-1.45,0) 2(1.45,0)
  silkscreen extent -2.4,-1.21 2.4,1.21, body extent -1.7,-0.9 1.7,0.9, height 1.35
3528-21 [mm] "Medium Density IPC, based on SM-782 section 8.4"
  rect 1.95x2.25 smd: 1(-1.375,0) 2(1.375,0)
  silkscreen extent -3.56,-1.5 1.9,1.5, body extent -1.85,-1.5 1.85,1.5, height 2.1
AssemblyNote [mil] "Assembly Note"
AssemblyNoteLabel [mil] "Assembly Note for PCB Labels"
CN2_MTB_P100_PD80_D1.1_S5.54X6.5_STACK [mil]
  rect 80x80 / inner round 80 / far side rect 80x80 hole 44: 1(-50,0)
  round 80 hole 44: 2(50,0)
  silkscreen extent -135,-128 100,145
CONN_1725711 [mm] "Phoenix Contact"
  rect 1.78x1.78 hole 1.1: 1(-8.89,0)
  round 1.78 hole 1.1: 2(-6.35,0) 3(-3.81,0) 4(-1.27,0) 5(1.27,0) 6(3.81,0) 7(6.35,0) 8(8.89,0)
  silkscreen extent -10.49,-3.6 10.4,4.09, body extent -10.39,-3.1 10.39,3.1, height 8.52
DBT0038A_M [mm] "TSSOP, 38-Leads, Body 9.7x4.4mm, Pitch 0.5mm, IPC Low Density"
  oval 2.05x0.3 smd: 1(-2.825,4.5) 2(-2.825,4) 3(-2.825,3.5) 4(-2.825,3) 5(-2.825,2.5) 6(-2.825,2) 7(-2.825,1.5) 8(-2.825,1) 9(-2.825,0.5) 10(-2.825,0) 11(-2.825,-0.5) 12(-2.825,-1) 13(-2.825,-1.5) 14(-2.825,-2) 15(-2.825,-2.5) 16(-2.825,-3) 17(-2.825,-3.5) 18(-2.825,-4) 19(-2.825,-4.5) 20(2.825,-4.5) 21(2.825,-4) 22(2.825,-3.5) 23(2.825,-3) 24(2.825,-2.5) 25(2.825,-2) 26(2.825,-1.5) 27(2.825,-1) 28(2.825,-0.5) 29(2.825,0) 30(2.825,0.5) 31(2.825,1) 32(2.825,1.5) 33(2.825,2) 34(2.825,2.5) 35(2.825,3) 36(2.825,3.5) 37(2.825,4) 38(2.825,4.5)
  silkscreen extent -2.95,-4.9 1.4,5.33, body extent -2.25,-4.9 2.25,4.9, height 1.2
DBV0005A_N [mm] "SOT23, 5-Leads, Body 2.9x1.6mm, Pitch 0.95mm, Lead Span 2.8mm, IPC Medium Density"
  rect 1.1x0.65 smd: 1(-1.2,0.95) 2(-1.2,0) 3(-1.2,-0.95) 4(1.2,-0.95) 5(1.2,0.95)
  silkscreen extent -2.41,-1.55 0.25,1.55, body extent -1.42,-1.46 1.42,1.46, height 1.08
DIO_SMB_BIAAAA [mm]
  rect 2.5x2.3 smd: 1(-2.15,0) 2(2.15,0)
  silkscreen extent -4.83,-1.97 2.29,2.54
FB0603 [mm]
  rect 0.95x1 smd: 1(-0.75,0) 2(0.75,0)
  silkscreen extent -0.8,-0.7 0.8,0.7
FID_TOP_40_80BA [mil]
  round 40 smd mask+20: 1(0,0)
  Top Layer region: 45.39,0 43.84,11.75 39.31,22.69 32.09,32.09 22.69,39.31 11.75,43.84 0,45.39 -11.75,43.84 -22.69,39.31 -32.09,32.09 -39.31,22.69 -43.84,11.75 -45.39,0 -43.84,-11.75 -39.31,-22.69 -32.09,-32.09 -22.69,-39.31 -11.75,-43.84 0,-45.39 11.75,-43.84 22.69,-39.31 32.09,-32.09 39.31,-22.69 43.84,-11.75
Label_650x200 [mil] "Thermal Transfer Label"
  silkscreen extent -325,-100 325,100, body extent -326,-101 326,101, height 1
LED0603AA [mil]
  rect 32x32 smd: 1(-32.48,0) 2(32.48,0)
  silkscreen extent -25,-16 45,70
"NY PMS 440 0025 PH"#1 [mil] "4-40 nylon screw and mounting hole"
  round 240 hole 128: 1(0,-13)
  body extent -130,-130 130,130, height 106
"NY PMS 440 0025 PH"#2 [mil] "4-40 nylon screw and mounting hole"
  round 240 hole 128: 1(-15,20)
  body extent -130,-130 130,130, height 106
"NY PMS 440 0025 PH"#3 [mil] "4-40 nylon screw and mounting hole"
  round 240 hole 128: 1(15,0)
  body extent -130,-130 130,130, height 106
"NY PMS 440 0025 PH"#4 [mil] "4-40 nylon screw and mounting hole"
  round 240 hole 128: 1(-15,0)
  body extent -130,-130 130,130, height 106
powerDI123 [mm] "Diodes Inc recommended land pattern, document number DS30628 Rev. 6-2"
  rect 2.2x1.4 smd: 1(-1.275,0)
  rect 0.9x1.4 smd: 2(1.275,0)
  silkscreen extent -3.1,-1.09 1.76,1.09, body extent -2.38,-0.97 1.52,0.96, height 1
sod-323 [mm] "NXP recommended land pattern"
  rect 0.6x0.6 smd: 1(-1.1,0) 2(1.1,0)
  silkscreen extent -2.05,-0.86 1.53,0.86, body extent -1.3,-0.67 1.3,0.68, height 1.1
SON_CSD17571Q2 [mm] "SON, MOSFET, N-CH, 30V, 22A, SON 2X2 MM"
  rect 0.4x0.455 smd mask+0.038: 1(-0.65,-0.923) 2(0,-0.923) 5(0,0.923) 6(-0.65,0.923)
  rect 0.4x0.455 smd: 3(0.65,-0.923) 4(0.65,0.923)
  rect 0.4x0.85 smd mask+0.038: 7(0.65,0.096)
  rect 1.05x1.1 smd mask+0.038: 8(-0.325,0)
  silkscreen extent -1.88,-1.09 1.1,1, body extent -1,-1 1,0.97, height 0.85
TI_Stacked_SolderMask_Small [mil]
  silkscreen extent -418,-98 418,98
TP1_PD40_D0.5_S50#1 [mil]
  round 40 hole 20: 1(0,0)
  silkscreen extent -25,-25 25,25
TP1_PD40_D0.5_S50#2 [mil]
  round 30 hole 16: 1(0,0)
  silkscreen extent -25,-25 25,25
